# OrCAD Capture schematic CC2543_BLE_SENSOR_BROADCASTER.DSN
size A4; title: CC2543 BLE Sensor Broadcaster; rev: 1.0.0
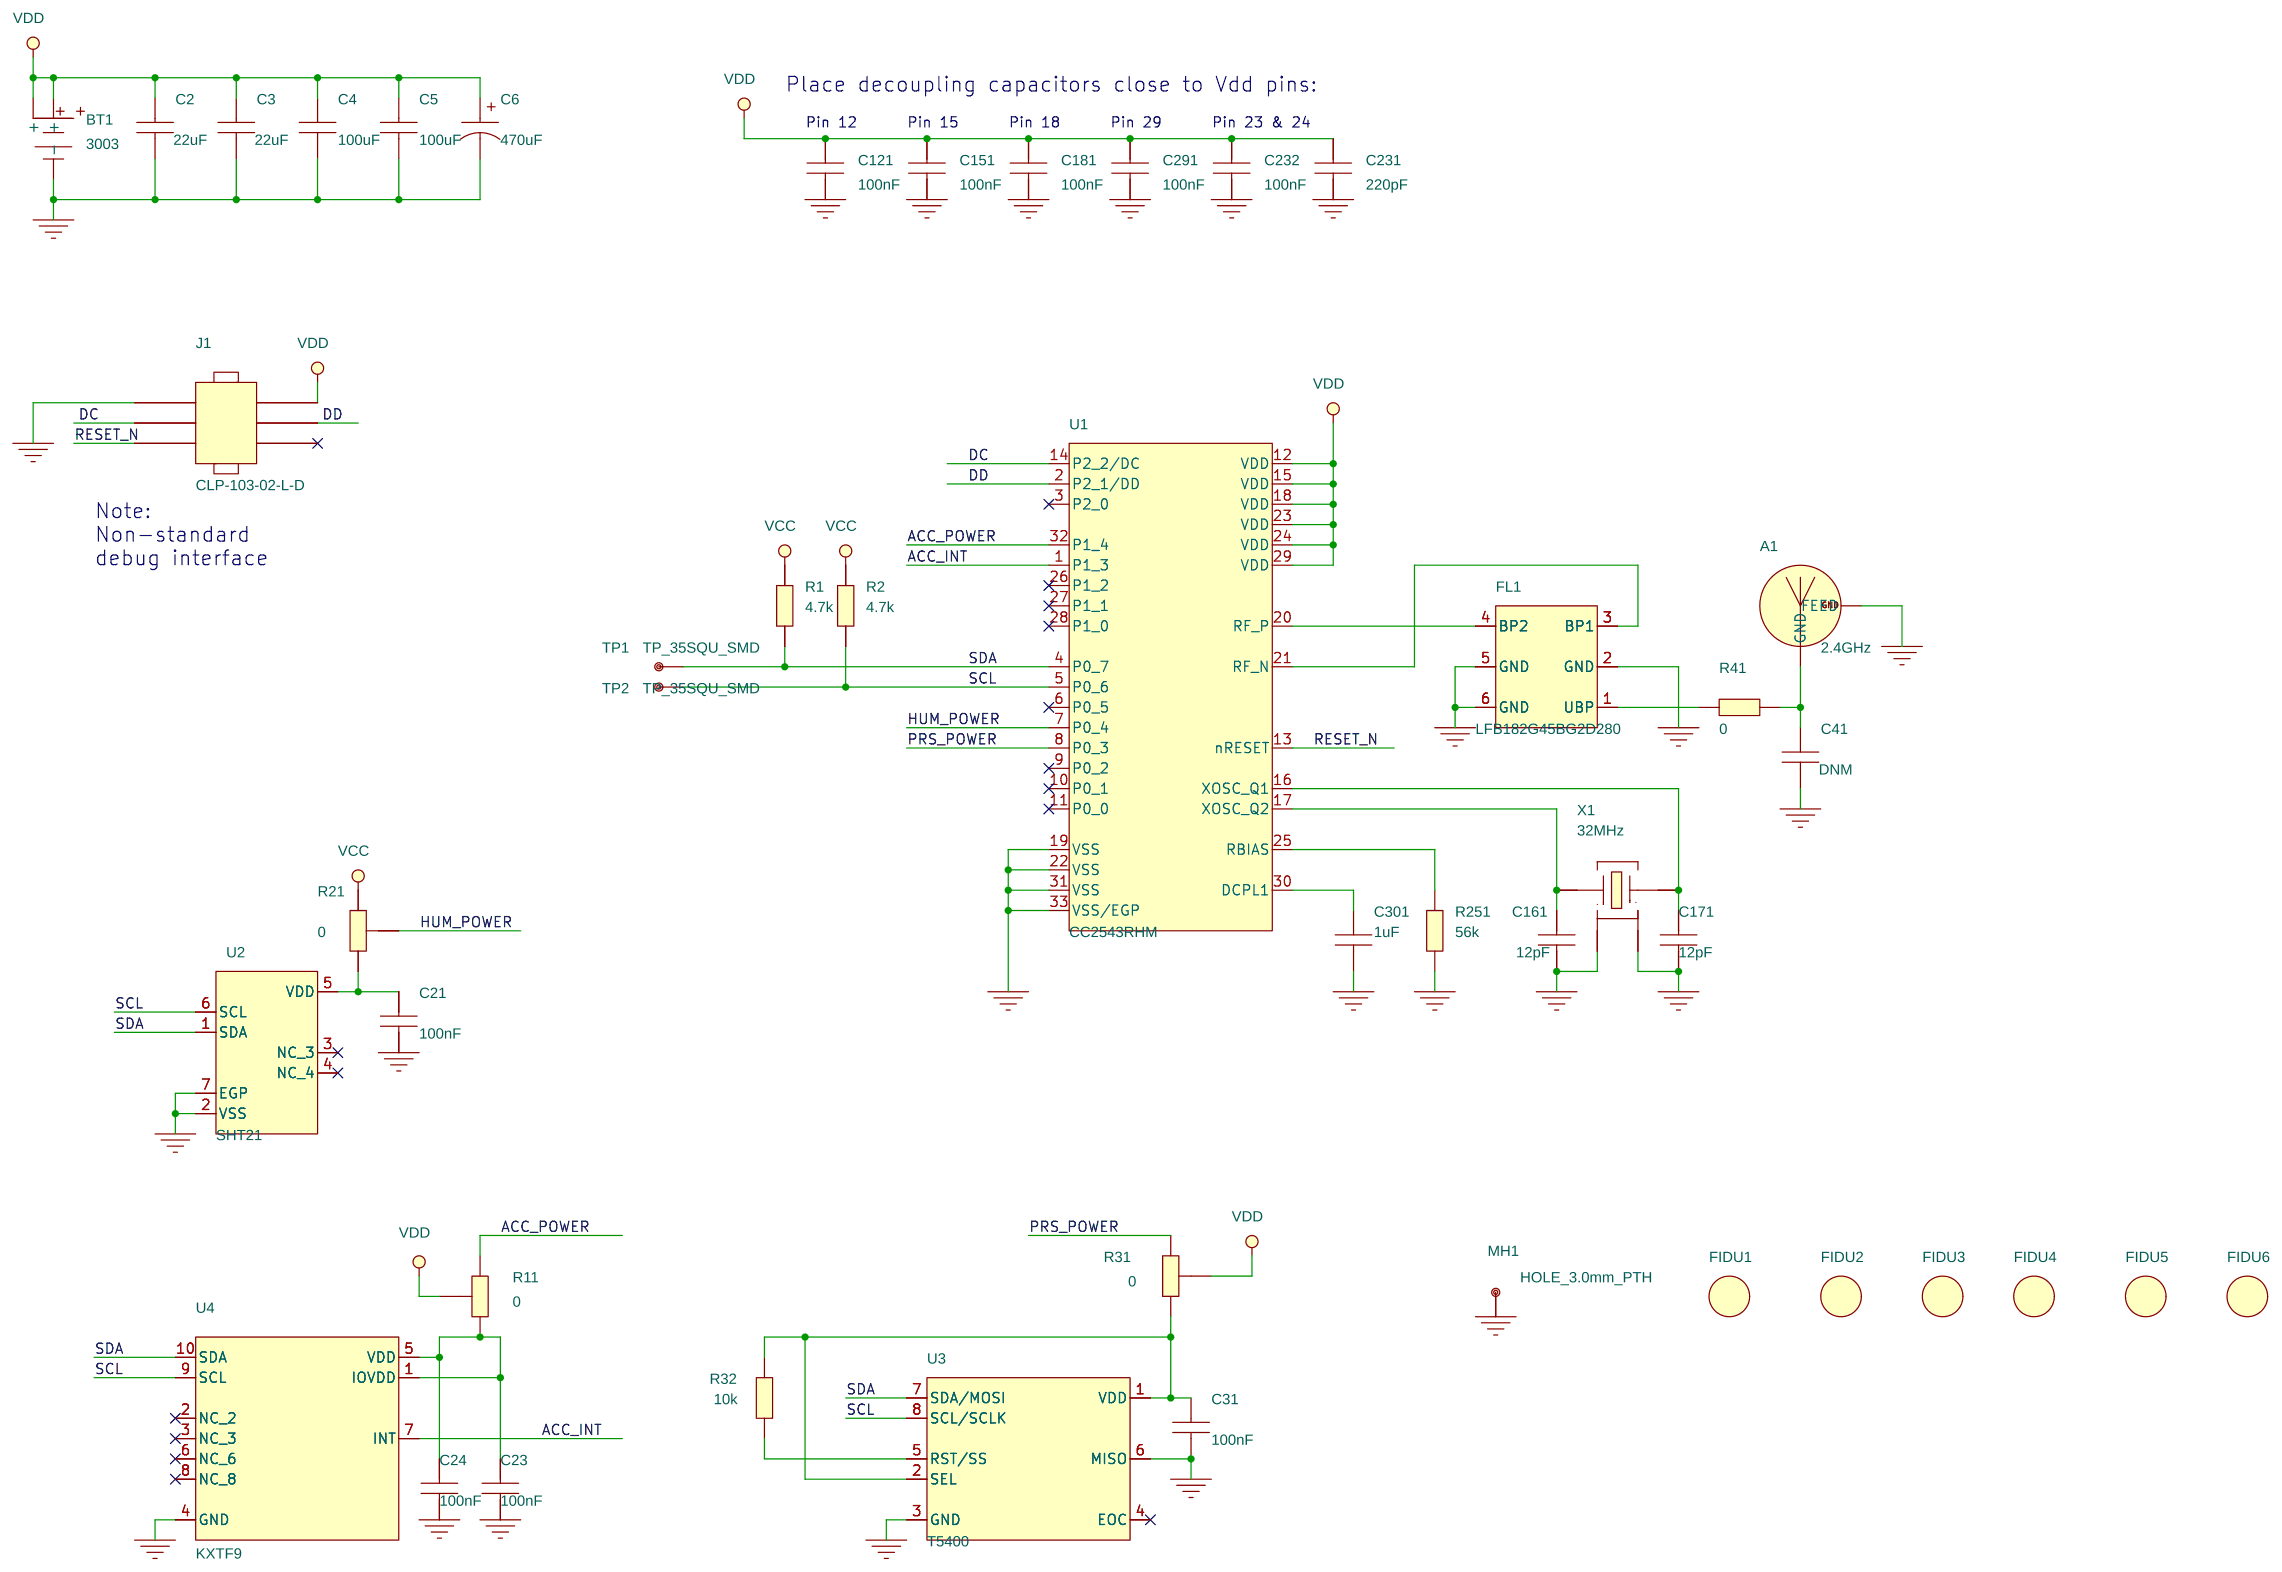
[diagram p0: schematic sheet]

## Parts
A1  2.4GHz  [ANTENNA_AN043CN]
BT1  3003  [BAT_3003C]
C2  22uF  [CAPC1608X90N]
C3  22uF  [CAPC1608X90N]
C4  100uF  [CAPC3216X180L]
C5  100uF  [CAPC3216X180L]
C6  470uF  [CAPMP6032X280L]
C21  100nF  [CAPC1005X60L]
C23  100nF  [CAPC1005X60L]
C24  100nF  [CAPC1005X60L]
C31  100nF  [CAPC1005X60L]
C41  DNM  [CAPC1005X60L]
C121  100nF  [CAPC1005X60L]
C151  100nF  [CAPC1005X60L]
C161  12pF  [CAPC1005X60L]
C171  12pF  [CAPC1005X60L]
C181  100nF  [CAPC1005X60L]
C231  220pF  [CAPC1005X60L]
C232  100nF  [CAPC1005X60L]
C291  100nF  [CAPC1005X60L]
C301  1uF  [CAPC1005X60L]
FIDU1  FIDU_1MM  [FID100X115]
FIDU2  FIDU_1MM  [FID100X115]
FIDU3  FIDU_1MM  [FID100X115]
FIDU4  FIDU_1MM  [FID100X115]
FIDU5  FIDU_1MM  [FID100X115]
FIDU6  FIDU_1MM  [FID100X115]
FL1  LFB182G45BG2D280  [FIL_LFB182G45BG2D280L]
J1  CLP-103-02-L-D  [SAMTEC_CLP10302LD-6L]
MH1  HOLE_3.0mm_PTH  [MTG300_360]
R1  4.7k  [RESC1005X40L]
R2  4.7k  [RESC1005X40L]
R11  0  [RESC1005X40BL]
R21  0  [RESC1005X40AL]
R31  0  [RESC1005X40BL]
R32  10k  [RESC1005X40L]
R41  0  [RESC1005X40L]
R251  56k  [RESC1005X40L]
TP1  TP_35SQU_SMD  [TP90SQWOPM_V2]
TP2  TP_35SQU_SMD  [TP90SQWOPM_V2]
U1  CC2543RHM  [QFNWB50P500X500X100-33CN]
U2  SHT21  [SON100P300X300X110-7L]
U3  T5400  [PSON71P223X278X75-8L]
U4  KXTF9  [QFNFC65P300X300X100-10N]
X1  32MHz  [XTAL_FA128L]

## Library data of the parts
A1 = ANTENNA_AN043: MECHANIC, SMALL SIZE 2.4GHz PCB ANTENNA, SMD; AutoDoc File: http://notefied-dynamic-precision.com/DB/Apps/Desktop/Item/Object.aspx?id=80208; Budget Currency: N/A; Budget Price: N/A; Datasheet URL 1: N/A; Datasheet URL 2: http://www.ti.com/lit/an/swra117d/swra117d.pdf; Definied Quality: N/A; Esd Level: N/A; FPLIST: ANTENNA_AN043AN_B,ANTENNA_AN043CN,; Lead Time: N/A; MPN: AN043; MPN Status: ACTIVE; MSL: N/A; MTBF: N/A; MTBF Standard: N/A; Manufacturer: TEXAS INSTRUMENTS; Mounting Type: SMD; NOTE Status: PREFERRED; Old Footprint: ANTENNA_AN043AN_B,ANTENNA_AN043CN; Packing Size: N/A; Packing Type: N/A; Part Number: 13-00290; Part Type: MECHANIC\ANTENNA; Revision: R002; RoHS Status: N/A; WEIGHT: N/A
BT1 = BATT_RETAINER: BATTERY,  PTH PCB LITHIUM COIN CELL BATTERY RETAINER, PTH; ALT_SYMBOLS: BAT_3003C,BAT_3003A; AutoDoc File: http://notefied-dynamic-precision.com/DB/Apps/Desktop/Item/Object.aspx?id=88220; Datasheet URL 2: http://www.keyelco.com/pdfs/M60/M60p7.pdf; FPLIST: BAT_3003B,BAT_3003C,BAT_3003A; MPN Status: ACTIVE; Manufacturer: KEYSTONE ELECTRONICS CORP; Max Oper Temp: +85DEGC; Min Oper Temp: -40DEGC; Mounting Type: PTH; NOTE Status: PREFERRED; Old Footprint: BAT_3003B; Packing Type: BULK; Part Number: 10-00019; Part Type: BATTERY\HOLDER; Revision: R001; RoHS Status: ROHS_COMPLIANT
C2 C3 = CAPACITOR: CAPACITOR, CERAMIC X5R, 22uF, 4V, -20%/+20%, -55DEGC/+85DEGC, 0603, SMD; ALT_SYMBOLS: CAPC1608X90L,CAPC1608X90M; AutoDoc File: http://notefied-dynamic-precision.com/DB/Apps/Desktop/Item/Object.aspx?id=86641; Budget Currency: EUR; Budget Price: 0.101; Datasheet URL 1: http://search.murata.co.jp/Ceramy/image/img/A01X/G101/ENG/GRM188R60G226MEA0-01.pdf; Datasheet URL 2: http://search.murata.co.jp/Ceramy/image/img/A01X/G101/ENG/GRM188R60G226MEA0-01.pdf; Dielectric Type: X5R; FPLIST: CAPC1608X90N,CAPC1608X90L,CAPC1608X90M; Lead Time: 14; MPN: GRM188R60G226MEA0D; MPN Status: ACTIVE; Manufacturer: MURATA; Max Oper Temp: +85DEGC; Max Tol: +20%; Min Oper Temp: -55DEGC; Min Tol: -20%; Mounting Type: SMD; NOTE Status: PREFERRED; PCB Package: 0603; Packing Size: 4000; Packing Type: TAPE_&_REEL; Part Number: 02-04481; Part Type: CAPACITOR\CERAMIC\0603; Revision: R001; RoHS Status: ROHS_COMPLIANT; Rtd Voltage: 4V; WEIGHT: 0.0063g
C4 C5 = CAPACITOR: CAPACITOR, CERAMIC X5R, 100uF, 6.3V, -20%/+20%, -55DEGC/+85DEGC, 1206, SMD; ALT_SYMBOLS: CAPC3216X180L,CAPC3216X180M; AutoDoc File: http://notefied-dynamic-precision.com/DB/Apps/Desktop/Item/Object.aspx?id=50587; Budget Currency: EUR; Budget Price: 0.407; Datasheet URL 1: http://search.murata.co.jp/Ceramy/image/img/A01X/G101/ENG/GRM31CR60J107ME39-01.pdf; Datasheet URL 2: http://search.murata.co.jp/Ceramy/image/img/A01X/G101/ENG/GRM31CR60J107ME39-01.pdf; Dielectric Type: X5R; FPLIST: CAPC3216X180N,CAPC3216X180L,CAPC3216X180M; Lead Time: 16; LifeCycle Status: GROWTH; MPN: GRM31CR60J107ME39L; MPN Status: ACTIVE; Manufacturer: MURATA; Max Oper Temp: +85DEGC; Max Tol: +20%; Min Oper Temp: -55DEGC; Min Tol: -20%; Mounting Type: SMD; NOTE Status: PREFERRED; Old Footprint: CAPC3216X180N,1206; PCB Package: 1206; Packing Size: 2000; Packing Type: TAPE_&_REEL; Part Number: 02-01436; Part Type: CAPACITOR\CERAMIC\1206; Revision: R003; RoHS Status: ROHS_COMPLIANT; Rtd Voltage: 6.3V; WEIGHT: 0.052g
C6 = CAPACITOR_POL: CAPACITOR, TANTALUM, 470uF, 4V, -10%/+10%, -55DEGC/+125DEGC, 6032-28, SMD; ALT_SYMBOLS: CAPMP6032X280L,CAPMP6032X280M; AutoDoc File: http://notefied-dynamic-precision.com/DB/Apps/Desktop/Item/Object.aspx?id=74200; Budget Currency: USD; Budget Price: 1.07; Datasheet URL 1: http://www.avx.com/docs/Catalogs/taj.pdf; Datasheet URL 2: http://www.avx.com/docs/Catalogs/taj.pdf; Dielectric Type: TANTALUM; FPLIST: CAPMP6032X280N,CAPMP6032X280L,CAPMP6032X280M; Lead Time: 10; MPN: TAJC477K004RNJ; MPN Status: ACTIVE; Manufacturer: AVX; Max Oper Temp: +125DEGC; Max Tol: +10%; Min Oper Temp: -55DEGC; Min Tol: -10%; Mounting Type: SMD; NOTE Status: PREFERRED; Old Footprint: CAPMP6032X280N,6032_CASEC_60X35X28; PCB Package: 6032-28; Packing Type: TAPE_&_REEL; Part Number: 02-02373; Part Type: CAPACITOR\TANTALUM\6032-28; Revision: R001; RoHS Status: ROHS_COMPLIANT; Rtd Voltage: 4V
C21 C23 C24 C31 C121 C151 C181 C232 C291 = CAPACITOR: CAPACITOR, CERAMIC X7R, 100nF, 10V, -10%/+10%, -55DEGC/+125DEGC, 0402, SMD; ALT_SYMBOLS: CAPC1005X60L,CAPC1005X60M; AutoDoc File: http://notefied-dynamic-precision.com/DB/Apps/Desktop/Item/Object.aspx?id=49911; Budget Currency: EUR; Budget Price: 0.016; Datasheet URL 1: http://search.murata.co.jp/Ceramy/image/img/PDF/ENG/GRM155R71A104KA01.pdf; Datasheet URL 2: http://search.murata.co.jp/Ceramy/image/img/PDF/ENG/GRM155R71A104KA01.pdf; Dielectric Type: X7R; FPLIST: CAPC1005X60N,CAPC1005X60L,CAPC1005X60M; Lead Time: 13; LifeCycle Status: GROWTH; MPN: GRM155R71A104KA01D; MPN Status: ACTIVE; Manufacturer: MURATA; Max Oper Temp: +125DEGC; Max Tol: +10%; Min Oper Temp: -55DEGC; Min Tol: -10%; Mounting Type: SMD; NOTE Status: PREFERRED; Old Footprint: CAPC1005X60N,0402; PCB Package: 0402; Packing Size: 10000; Packing Type: TAPE_&_REEL; Part Number: 02-00760; Part Type: CAPACITOR\CERAMIC\0402; Revision: R003; RoHS Status: ROHS_COMPLIANT; Rtd Voltage: 10V
C41 = CAPACITOR: CAPACITOR, DO NOT MOUNT, 0402, SMD; ALT_SYMBOLS: CAPC1005X60L,CAPC1005X60M; AutoDoc File: https://notefied-dynamic-precision.com/NotefiedWebServices/AutoDocs.aspx?itemid=50472; FPLIST: CAPC1005X60N,CAPC1005X60L,CAPC1005X60M; Old Footprint: CAPC1005X60N,0402; Part Number: 02-01321; Part Type: CAPACITOR\CERAMIC\0402; Revision: R003
C161 C171 = CAPACITOR: CAPACITOR, CERAMIC C0G/NP0, 12pF, 50V, -5%/+5%, -55DEGC/+125DEGC, 0402, SMD; ALT_SYMBOLS: CAPC1005X60L,CAPC1005X60M; AutoDoc File: http://notefied-dynamic-precision.com/DB/Apps/Desktop/Item/Object.aspx?id=84867; Datasheet URL 1: http://search.murata.co.jp/Ceramy/image/img/PDF/ENG/GRM1555C1H120JA01.pdf; Datasheet URL 2: http://search.murata.co.jp/Ceramy/image/img/PDF/ENG/GRM1555C1H120JA01.pdf; Dielectric Type: C0G/NP0; FPLIST: CAPC1005X60N,CAPC1005X60L,CAPC1005X60M; MPN: GRM1555C1H120JA01D; MPN Status: ACTIVE; Manufacturer: MURATA; Max Oper Temp: +125DEGC; Max TC: +30PPM/DEGC; Max Tol: +5%; Min Oper Temp: -55DEGC; Min TC: -30PPM/DEGC; Min Tol: -5%; Mounting Type: SMD; NOTE Status: PREFERRED; Old Footprint: CAPC1005X60N; PCB Package: 0402; Packing Size: 10000; Packing Type: TAPE_&_REEL; Part Number: 02-04168; Part Type: CAPACITOR\CERAMIC\0402; Revision: R000; RoHS Status: ROHS_COMPLIANT; Rtd Voltage: 50V
C231 = CAPACITOR: CAPACITOR, CERAMIC C0G/NP0, 220pF, 50V, -5%/+5%, -55DEGC/+125DEGC, 0402, SMD; ALT_SYMBOLS: CAPC1005X60L,CAPC1005X60M; AutoDoc File: http://notefied-dynamic-precision.com/DB/Apps/Desktop/Item/Object.aspx?id=50427; Budget Currency: EUR; Budget Price: 0.034; Datasheet URL 1: http://www.murata.com/catalog/c02e.pdf; Datasheet URL 2: http://www.murata.com/catalog/c02e.pdf; Dielectric Type: C0G/NP0; FPLIST: CAPC1005X60N,CAPC1005X60L,CAPC1005X60M; Lead Time: 12; LifeCycle Status: GROWTH; MPN: GRM1555C1H221JA01D; MPN Status: ACTIVE; Manufacturer: MURATA; Max Oper Temp: +125DEGC; Max Tol: +5%; Min Oper Temp: -55DEGC; Min Tol: -5%; Mounting Type: SMD; NOTE Status: PREFERRED; Old Footprint: CAPC1005X60N,0402; PCB Package: 0402; Packing Size: 10000; Packing Type: TAPE_&_REEL; Part Number: 02-01276; Part Type: CAPACITOR\CERAMIC\0402; Revision: R001; RoHS Status: ROHS_COMPLIANT; Rtd Voltage: 50V
C301 = CAPACITOR: CAPACITOR, CERAMIC X5R, 1uF, 10V, -10%/+10%, -55DEGC/+85DEGC, 0402, SMD; ALT_SYMBOLS: CAPC1005X60L,CAPC1005X60M; AutoDoc File: http://notefied-dynamic-precision.com/DB/Apps/Desktop/Item/Object.aspx?id=74236; Budget Currency: EUR; Budget Price: 0.066; Datasheet URL 1: http://search.murata.co.jp/Ceramy/image/img/PDF/ENG/GRM155R61A105KE15.pdf; Datasheet URL 2: http://search.murata.co.jp/Ceramy/image/img/PDF/ENG/GRM155R61A105KE15.pdf; Dielectric Type: X5R; FPLIST: CAPC1005X60N,CAPC1005X60L,CAPC1005X60M; MPN: GRM155R61A105KE15D; MPN Status: ACTIVE; Manufacturer: MURATA; Max Oper Temp: +85DEGC; Max Tol: +10%; Min Oper Temp: -55DEGC; Min Tol: -10%; Mounting Type: SMD; NOTE Status: PREFERRED; Old Footprint: CAPC1005X60N,0402; PCB Package: 0402; Packing Size: 10000; Packing Type: TAPE_&_REEL; Part Number: 02-02381; Part Type: CAPACITOR\CERAMIC\0402; Revision: R002; RoHS Status: ROHS_COMPLIANT; Rtd Voltage: 10V
FIDU1-FIDU6 = FIDMARK: FIDUCIAL MARK, ROUND 1MM; AutoDoc File: https://notefied-dynamic-precision.com/NotefiedWebServices/AutoDocs.aspx?itemid=74548; Part Number: 19-00111; Part Type: NON_COMPONENT\FIDUCIAL; Revision: R001
FL1 = FILTER_LFB_6PIN: FILTER, LC, BAND PASS FILTER@50R, 2450MHz, -40DEGC/+85DEGC, 0603, SMD; ALT_SYMBOLS: FIL_LFB182G45BG2D280L,FIL_LFB182G45BG2D280M; AutoDoc File: http://notefied-dynamic-precision.com/DB/Apps/Desktop/Item/Object.aspx?id=88217; Budget Currency: EUR; Budget Price: 0.153; Datasheet URL 2: http://search.murata.co.jp/Ceramy/image/img/w_hinm/S0296E.pdf; FPLIST: FIL_LFB182G45BG2D280N,FIL_LFB182G45BG2D280L,FIL_LFB182G45BG2D280M; Frequency: 2450MHz; Impedance: 50; Lead Time: 9; MPN Status: ACTIVE; Manufacturer: MURATA; Max Oper Temp: +85DEGC; Min Oper Temp: -40DEGC; Mounting Type: SMD; NOTE Status: PREFERRED; Old Footprint: FIL_LFB182G45BG2D280N; PCB Package: 0603; Packing Size: 4000; Packing Type: TAPE_&_REEL; Part Number: 04-00513; Part Type: FILTER\SIGNAL; Revision: R001; RoHS Status: ROHS_COMPLIANT; Rtd Power: 0.5W
J1 = CONN_HEADER_2X3: CONNECTOR, SHROUDED HEADER, FEMALE, STRAIGHT, 2 ROWS, 6 PINS, PITCH 1.27MM, SMD; ALT_SYMBOLS: SAMTEC_CLP10302LD-6L,SAMTEC_CLP10302LD-6M; AutoDoc File: http://notefied-dynamic-precision.com/DB/Apps/Desktop/Item/Object.aspx?id=84304; Datasheet URL 1: http://www.samtec.com/ftppub/pdf/CLP_SM.PDF; Datasheet URL 2: http://www.samtec.com/ftppub/pdf/CLP_SM.PDF; FPLIST: SAMTEC_CLP10302LD-6N,SAMTEC_CLP10302LD-6L,SAMTEC_CLP10302LD-6M; MPN Status: ACTIVE; Manufacturer: SAMTEC; Max Oper Temp: +125DEGC; Min Oper Temp: -55DEGC; Mounting Type: SMD; NOTE Status: PREFERRED; No Of Pos: 6; No Of Rows: 2; Old Footprint: SAMTEC_CLP10302LD-6N; Part Number: 06-02051; Part Type: CONNECTOR\HEADER; Pitch: 1.27mm; Revision: R001; RoHS Status: ROHS_COMPLIANT; Rtd Current: 1.75A
MH1 = HOLE_PTH: HOLE 3.0mm, PLATED THROUGH HOLE; AutoDoc File: https://notefied-dynamic-precision.com/NotefiedWebServices/AutoDocs.aspx?itemid=57360; FPLIST: MTG300_360,HOLE_236CIR118_30,; Old Footprint: MTG300_360,HOLE_236CIR118_30; Part Number: 19-00081; Part Type: NON_COMPONENT\HOLE\PLATED; Revision: R001
R1 R2 = RESISTOR: RESISTOR, THICK FILM, 4.7k, -1%/+1%, 0.063W, 50V, -55DEGC/+155DEGC, 0402, SMD; ALT_SYMBOLS: RESC1005X40L,RESC1005X40M; AutoDoc File: http://notefied-dynamic-precision.com/DB/Apps/Desktop/Item/Object.aspx?id=76740; Budget Currency: USD; Budget Price: 0.00244; FPLIST: RESC1005X40N,RESC1005X40L,RESC1005X40M; LifeCycle Status: ACTIVE; MPN: RESISTOR_0402_4.7k_+/-1%_50V_0.063W_M_+/-100PPM; MPN Status: ACTIVE; Manufacturer: Manufacturer selection; Max Oper Temp: +155DEGC; Max TC: +100PPM/DEGC; Max Tol: +1%; Min Oper Temp: -55DEGC; Min TC: -100PPM/DEGC; Min Tol: -1%; Mounting Type: SMD; NOTE Status: PREFERRED; Old Footprint: RESC1005X40N; PCB Package: 0402; Packing Size: 10000; Packing Type: TAPE_&_REEL; Part Number: 01-12685; Part Type: RESISTOR\0402\PRECISION; Resistor Type: THICK FILM; Revision: R002; RoHS Status: ROHS_COMPLIANT; Rtd Power: 0.063W; Rtd Voltage: 50V
R11 R21 R31 = RESISTOR_3PORTS: RESISTOR, JUMPER, 3 PORTS, -55DEGC/+155DEGC, 0402, SMD; ALT_SYMBOLS: RESC1005X40AL,RESC1005X40AM,RESC1005X40BL,RESC1005X40BM; AutoDoc File: http://notefied-dynamic-precision.com/DB/Apps/Desktop/Item/Object.aspx?id=84964; Datasheet URL 1: http://www.koaspeer.com/catimages/Products/RK73Z/RK73Z.pdf; Datasheet URL 2: http://www.koaspeer.com/catimages/Products/RK73Z/RK73Z.pdf; FPLIST: RESC1005X40AN,RESC1005X40BN,RESC1005X40AL,RESC1005X40AM,RESC1005X40BL,RESC1005X40BM; Lead Time: 14; LifeCycle Status: ACTIVE; MPN: RK73Z1ETTP; MPN Status: ACTIVE; Manufacturer: KOA SPEER; Max Oper Temp: +155DEGC; Min Oper Temp: -55DEGC; Mounting Type: SMD; NOTE Status: PREFERRED; Old Footprint: RESC1005X40AN,RESC1005X40BN; PCB Package: 0402; Part Number: 01-16574; Part Type: RESISTOR\0402; Resistor Type: THICK FILM; Revision: R001; RoHS Status: ROHS_COMPLIANT
R32 = RESISTOR: RESISTOR, THICK FILM, 10k, -1%/+1%, 0.063W, 50V, -55DEGC/+155DEGC, 0402, SMD; ALT_SYMBOLS: RESC1005X40L,RESC1005X40M; AutoDoc File: http://notefied-dynamic-precision.com/DB/Apps/Desktop/Item/Object.aspx?id=76778; Budget Currency: USD; Budget Price: 0.00244; FPLIST: RESC1005X40N,RESC1005X40L,RESC1005X40M; LifeCycle Status: ACTIVE; MPN: RESISTOR_0402_10k_+/-1%_50V_0.063W_M_+/-100PPM; MPN Status: ACTIVE; Manufacturer: Manufacturer selection; Max Oper Temp: +155DEGC; Max TC: +100PPM/DEGC; Max Tol: +1%; Min Oper Temp: -55DEGC; Min TC: -100PPM/DEGC; Min Tol: -1%; Mounting Type: SMD; NOTE Status: PREFERRED; Old Footprint: RESC1005X40N; PCB Package: 0402; Packing Size: 10000; Packing Type: TAPE_&_REEL; Part Number: 01-12723; Part Type: RESISTOR\0402\PRECISION; Resistor Type: THICK FILM; Revision: R002; RoHS Status: ROHS_COMPLIANT; Rtd Power: 0.063W; Rtd Voltage: 50V
R41 = RESISTOR: RESISTOR, THICK FILM, 0, -1%/+1%, 0.063W, 50V, -55DEGC/+155DEGC, 0402, SMD; ALT_SYMBOLS: RESC1005X40L,RESC1005X40M; AutoDoc File: http://notefied-dynamic-precision.com/DB/Apps/Desktop/Item/Object.aspx?id=80585; Budget Currency: USD; Budget Price: 0.00244; FPLIST: RESC1005X40N,RESC1005X40L,RESC1005X40M; LifeCycle Status: ACTIVE; MPN: RESISTOR_0402_0_+/-1%_50V_0.063W_M_+/-100PPM; MPN Status: ACTIVE; Manufacturer: Manufacturer selection; Max Oper Temp: +155DEGC; Max TC: +100PPM/DEGC; Max Tol: +1%; Min Oper Temp: -55DEGC; Min TC: -100PPM/DEGC; Min Tol: -1%; Mounting Type: SMD; NOTE Status: PREFERRED; Old Footprint: RESC1005X40N; PCB Package: 0402; Packing Size: 10000; Packing Type: TAPE_&_REEL; Part Number: 01-15504; Part Type: RESISTOR\0402\PRECISION; Resistor Type: THICK FILM; Revision: R002; RoHS Status: ROHS_COMPLIANT; Rtd Power: 0.063W; Rtd Voltage: 50V
R251 = RESISTOR: RESISTOR, THICK FILM, 56k, -1%/+1%, 0.063W, 50V, -55DEGC/+155DEGC, 0402, SMD; ALT_SYMBOLS: RESC1005X40L,RESC1005X40M; AutoDoc File: http://notefied-dynamic-precision.com/DB/Apps/Desktop/Item/Object.aspx?id=85449; Datasheet URL 1: http://www.koaspeer.com/catimages/Products/RK73H/RK73H.pdf; Datasheet URL 2: http://www.koaspeer.com/catimages/Products/RK73H/RK73H.pdf; FPLIST: RESC1005X40N,RESC1005X40L,RESC1005X40M; MPN: RK73H1ETTP5602F; MPN Status: ACTIVE; Manufacturer: KOA SPEER; Max Oper Temp: +155DEGC; Max TC: +100PPM/DEGC; Max Tol: +1%; Min Oper Temp: -55DEGC; Min TC: -100PPM/DEGC; Min Tol: -1%; Mounting Type: SMD; NOTE Status: PREFERRED; Old Footprint: RESC1005X40N; PCB Package: 0402; Part Number: 01-16848; Part Type: RESISTOR\0402\PRECISION; Resistor Type: THICK FILM; Revision: R001; RoHS Status: ROHS_COMPLIANT; Rtd Power: 0.063W; Rtd Voltage: 50V
TP1 TP2 = TEST_POINT: TESTPOINT, SQU 0.9MM, SMD; AutoDoc File: https://notefied-dynamic-precision.com/NotefiedWebServices/AutoDocs.aspx?itemid=57476; FPLIST: TP90SQWOPM_V2,; Old Footprint: TP90SQWOPM_V2,TP_35SQU35_SMD; Part Number: 19-00197; Part Type: NON_COMPONENT\TEST_POINT; Revision: R002
U1 = IC_RF_CC2543_QFN32_0: IC, ANALOG RF, SYSTEM-ON-CHIP FOR 2.4-GHz RF APPLICATIONS, 2V TO 3.6V, VQFN32, SMD; ALT_SYMBOLS: QFNWB50P500X500X100-33CL,QFNWB50P500X500X100-33CM; AutoDoc File: http://notefied-dynamic-precision.com/DB/Apps/Desktop/Item/Object.aspx?id=87336; Budget Currency: USD; Budget Price: 1.75; Datasheet URL 1: http://www.ti.com/lit/ds/symlink/cc2543.pdf; Datasheet URL 2: http://www.ti.com/lit/ds/symlink/cc2543.pdf; Lead Time: N/A; MPN: CC2543RHMR; MPN Status: PRELIMINARY; MSL: 3; MTBF: 3.3* 10^8; Manufacturer: TEXAS INSTRUMENTS; Max Oper Temp: +85DEGC; Min Oper Temp: -40DEGC; Mounting Type: SMD; NOTE Status: PREFERRED; PCB Package: VQFN32; Packing Size: 3000; Packing Type: TAPE_&_REEL; Part Number: 18-28144; Part Type: IC\ANALOG\RF\TRANSCEIVER; Revision: R001; RoHS Status: ROHS_COMPLIANT; Rtd Voltage: 2V TO 3.6V; WEIGHT: 0.074g
U2 = IC_SENSOR_SHT21: IC, DIGITAL, HUMIDITY AND TEMPERATURE SENSOR 8/12BIT, 3.0V, DFN8, SMD; ALT_SYMBOLS: SON100P300X300X110-7L,SON100P300X300X110-7M; AutoDoc File: http://notefied-dynamic-precision.com/DB/Apps/Desktop/Item/Object.aspx?id=84154; Budget Currency: EUR; Budget Price: 12.60; Datasheet URL 1: N/A; Datasheet URL 2: http://www.sensirion.com/fileadmin/user_upload/customers/sensirion/Dokumente/Humidity/Sensirion_Humidity_SHT21_Datasheet_V3.pdf; Definied Quality: INDUSTRIAL; Esd Level: HBM 4kV; FPLIST: SON100P300X300X110-7N,SON100P300X300X110-7L,SON100P300X300X110-7M; Lead Time: 7; MPN Status: ACTIVE; MSL: 1; MTBF: N/A; MTBF Standard: N/A; Manufacturer: SENSIRION; Max Oper Temp: +125DEGC; Min Oper Temp: -40DEGC; Mounting Type: SMD; NOTE Status: PREFERRED; Old Footprint: SON100P300X300X110-7N; PCB Package: DFN8; Packing Size: 400; Packing Type: TAPE_&_REEL; Part Number: 18-27466; Part Type: IC\TRANSDUCER\TEMPERATURE; Revision: R002; RoHS Status: ROHS_COMPLIANT; Rtd Voltage: 3V; WEIGHT: 0.025g
U3 = IC_PERIPH_T5400_PSON8: IC, TRANSDUCER, BAROMETRIC PRESSURE SENSOR, 1.7V TO 3.6V, PSON8, SMD; ALT_SYMBOLS: PSON71P223X278X75-8L,PSON71P223X278X75-8M; AutoDoc File: http://notefied-dynamic-precision.com/DB/Apps/Desktop/Item/Object.aspx?id=88215; Datasheet URL 2: http://www.epcos.com/inf/57/ds/T5400.pdf; FPLIST: PSON71P223X278X75-8N,PSON71P223X278X75-8L,PSON71P223X278X75-8M; MPN Status: ACTIVE; MSL: 3; Manufacturer: EPCOS; Max Oper Temp: +85DEGC; Min Oper Temp: -30DEGC; Mounting Type: SMD; NOTE Status: PREFERRED; Old Footprint: PSON71P223X278X75-8N; PCB Package: PSON8; Part Number: 18-28347; Part Type: IC\TRANSDUCER\PRESSURE; Revision: R001; RoHS Status: ROHS_COMPLIANT; Rtd Voltage: 1.7V TO 3.6V
U4 = IC_ACC_KXTF9_LGA10: IC, TRANSDUCER, TRI-AXIS DIGITAL ACCELEROMETER, 1.8V TO 3.6V, LGA10, SMD; ALT_SYMBOLS: QFNFC65P300X300X100-10,QFNFC65P300X300X100-10M; AutoDoc File: http://notefied-dynamic-precision.com/DB/Apps/Desktop/Item/Object.aspx?id=87910; Datasheet URL 1: http://www.kionix.com/sites/default/files/KXTF9-1026%20Specifications%20Rev%206.pdf; Datasheet URL 2: http://www.kionix.com/sites/default/files/KXTF9-1026%20Specifications%20Rev%206.pdf; FPLIST: QFNFC65P300X300X100-10N,QFNFC65P300X300X100-10,QFNFC65P300X300X100-10M; MPN: KXTF9-1026; MPN Status: ACTIVE; Manufacturer: KIONIX; Max Oper Temp: +85DEGC; Min Oper Temp: -40DEGC; Mounting Type: SMD; NOTE Status: PREFERRED; PCB Package: LGA10; Part Number: 18-28272; Part Type: IC\TRANSDUCER\ACCELERATION; Revision: R001; RoHS Status: ROHS_COMPLIANT; Rtd Voltage: 1.8V TO 3.6V
X1 = XTAL_4: CRYSTAL, OSCILATOR, 32MHz, 10pF, -10PPM/+10PPM, -40DEGC/+85DEGC, SMD; ALT_SYMBOLS: XTAL_FA128L,XTAL_FA128M; AutoDoc File: http://notefied-dynamic-precision.com/DB/Apps/Desktop/Item/Object.aspx?id=85460; Capacitance: 10pF; Datasheet URL 1: http://www.epsontoyocom.co.jp/english/product/Crystal/set02/fa128/index.html; Datasheet URL 2: http://ndap3-net.ebz.epson.co.jp/w/www/PDFS/epdoc_qd.nsf/85a4e2c523a1f89349257068002f9e30/255cb2884010a1f9492571f0004c7d72/$FILE/FA-128_E107.pdf; FPLIST: XTAL_FA128N,XTAL_FA128L,XTAL_FA128M; MPN: FA-128 32MHz 10pF 10PPM; MPN Status: ACTIVE; Manufacturer: Epson Toyocom; Max Oper Temp: +85DEGC; Max Tol: +10PPM; Min Oper Temp: -40DEGC; Min Tol: -10PPM; Mounting Type: SMD; NOTE Status: PREFERRED; Old Footprint: XTAL_FA128N; PCB Package: SMD; Part Number: 12-00422; Part Type: CRYSTAL\OSCILLATOR\MEMS; Revision: R001; RoHS Status: ROHS_COMPLIANT

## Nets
GND: A1.2(FEED) BT1.2(-) C2.2 C3.2 C4.2 C5.2 C6.2 C21.2 C23.2 C24.2 C31.2 C41.2 C121.2 C151.2 C161.2 C171.2 C181.2 C231.2 C232.2 C291.2 C301.2 FL1.2(GND) FL1.5(GND) FL1.6(GND) J1.2 MH1.1 R251.1 U1.19(VSS) U1.22(VSS) U1.31(VSS) U1.33(VSS/EGP) U2.2(VSS) U2.7(EGP) U3.3(GND) U3.6(MISO) U4.4(GND) X1.2 X1.4
VDD: BT1.1(+) BT1.3(+) C2.1 C3.1 C4.1 C5.1 C6.1 C121.1 C151.1 C181.1 C231.1 C232.1 C291.1 J1.1 R1.2 R2.2 R11.3 R21.1 R31.3 U1.12(VDD) U1.15(VDD) U1.18(VDD) U1.23(VDD) U1.24(VDD) U1.29(VDD)
ACC_INT: U1.1(P1_3) U4.7(INT)
ACC_POWER: R11.1 U1.32(P1_4)
DC: J1.4 U1.14(P2_2/DC)
DD: J1.3 U1.2(P2_1/DD)
HUM_POWER: R21.3 U1.7(P0_4)
PRS_POWER: R31.1 U1.8(P0_3)
RESET_N: J1.6 U1.13(nRESET)
SCL: R2.1 TP2.1 U1.5(P0_6) U2.6(SCL) U3.8(SCL/SCLK) U4.9(SCL)
SDA: R1.1 TP1.1 U1.4(P0_7) U2.1(SDA) U3.7(SDA/MOSI) U4.10(SDA)
N174685: FL1.4(BP2) U1.20(RF_P)
N174700: FL1.3(BP1) U1.21(RF_N)
N176560: R251.2 U1.25(RBIAS)
N176676: C301.1 U1.30(DCPL1)
N177477: C161.1 U1.17(XOSC_Q2) X1.1
N177564: C171.1 U1.16(XOSC_Q1) X1.3
N205771: C21.1 R21.2 U2.5(VDD)
N205894: C31.1 R31.2 R32.2 U3.1(VDD) U3.2(SEL)
N306707: FL1.1(UBP) R41.2
N306709: A1.1(GND) C41.1 R41.1
N309917: C23.1 C24.1 R11.2 U4.1(IOVDD) U4.5(VDD)
N318900: R32.1 U3.5(RST/SS)

Not connected (* = marked no-connect by the designer): FIDU1 1; FIDU2 1; FIDU3 1; FIDU4 1; FIDU5 1; FIDU6 1; J1 5*; U1 3(P2_0)* 6(P0_5)* 9(P0_2)* 10(P0_1)* 11(P0_0)* 26(P1_2)* 27(P1_1)* 28(P1_0)*; U2 3(NC)* 4(NC)*; U3 4(EOC)*; U4 2(NC)* 3(NC)* 6(NC)* 8(NC)*

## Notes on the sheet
- Place decoupling capacitors close to Vdd pins:
- Pin 12
- Pin 15
- Pin 18
- Pin 29
- Pin 23 & 24
- Note:
  Non-standard
  debug interface
